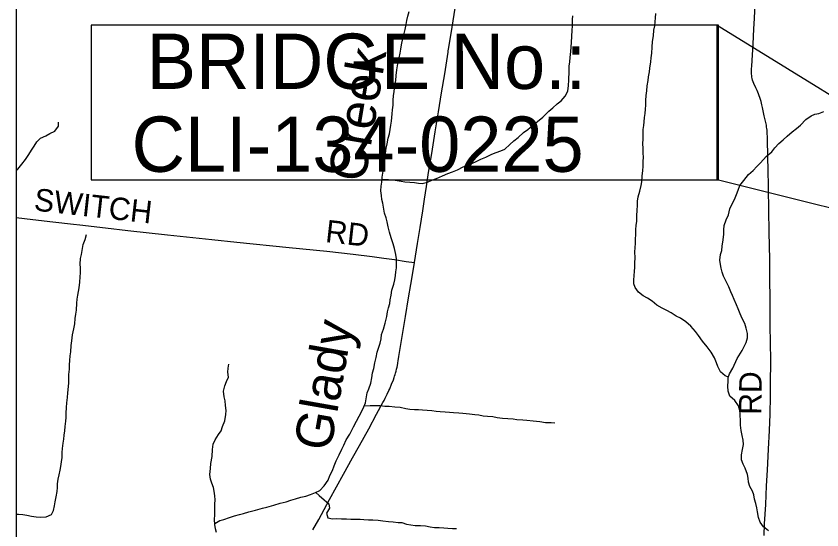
# Model space of a CAD drawing. Extents: x 0 to 48.6, y 0 to 22.
# Drawn here: x 2.1 to 4.141, y 17.154 to 18.455 of the extents above; entities that cross this region are included whole.
import ezdxf

# ---------------------------------------------------------------- set-up
doc = ezdxf.new("R2010")
doc.units = 0
for name, color, linetype in [('GM_X_Corporation', 7, 'Continuous'), ('GM_X_County_Road', 7, 'Continuous'), ('GM_X_County_Road_Text', 7, 'Continuous'), ('GM_X_Minor_River', 7, 'Continuous'), ('GM_X_Minor_River_Text', 7, 'Continuous'), ('GM_X_Township_Road', 7, 'Continuous'), ('GM_X_Township_Road_Text', 7, 'Continuous'), ('SH_Data', 7, 'Continuous'), ('SH_Masking', 7, 'Continuous'), ('SH_Text', 7, 'Continuous')]:
    doc.layers.add(name, color=color, linetype=linetype)

msp = doc.modelspace()

# ---------------------------------------------------------------- linework, layer by layer
at = {"layer": 'GM_X_Corporation'}
for points in [[(8.9, 20.9), (2.1, 20.9), (2.1, 14.1)], [(5.5264, 17.0064), (5.8387, 17.2541), (6.5365, 17.7727), (6.4996, 17.9212), (6.3396, 18.6531), (6.2759, 18.9159), (6.0412, 19.8859), (5.8236, 20.7829), (5.795, 20.9), (2.1, 20.9), (2.1, 14.1)]]:
    msp.add_lwpolyline(points, dxfattribs=at)
at = {"layer": 'GM_X_County_Road'}
for points in [[(3.1088, 17.8315), (3.1166, 17.8799), (3.123, 17.9197), (3.1297, 17.9627), (3.134, 17.9922), (3.1391, 18.0235), (3.1446, 18.0591), (3.1526, 18.1076), (3.1614, 18.1622), (3.1699, 18.213), (3.1775, 18.2609), (3.1855, 18.3093), (3.194, 18.3643), (3.1945, 18.3676), (3.1951, 18.3714), (3.2016, 18.4112), (3.2071, 18.4437), (3.217, 18.5088)], [(3.9943, 17.1401), (3.9958, 17.1693), (3.9984, 17.2189), (4.0007, 17.266), (4.0029, 17.3057), (4.0055, 17.3591), (4.008, 17.4062), (4.0095, 17.4472), (4.0105, 17.4932), (4.011, 17.5379), (4.0111, 17.569), (4.0103, 17.6429), (4.0099, 17.6566), (4.0098, 17.6609), (4.01, 17.6758), (4.0096, 17.7305), (4.0093, 17.7983), (4.0088, 17.8387), (4.0075, 17.9082), (4.0068, 17.9642), (4.0056, 18.0201), (4.0046, 18.0704), (4.004, 18.0934), (4.0028, 18.1493), (4.0024, 18.1582), (4.0023, 18.1617), (4.0018, 18.1665), (4.0014, 18.1704), (4.0009, 18.1739), (4.0005, 18.1766), (4.0001, 18.1791), (3.9987, 18.1864), (3.995, 18.2028), (3.9903, 18.224), (3.9888, 18.2307), (3.9878, 18.2348), (3.9867, 18.2392), (3.9852, 18.2443), (3.9837, 18.2494), (3.9821, 18.2537), (3.9804, 18.2582), (3.9785, 18.2625), (3.9766, 18.2667), (3.975, 18.27), (3.9734, 18.2735), (3.9682, 18.2847), (3.9666, 18.289), (3.9654, 18.2931), (3.9642, 18.2976), (3.9636, 18.3012), (3.9631, 18.3054), (3.9629, 18.3088), (3.9627, 18.3122), (3.9628, 18.3175), (3.9628, 18.3215), (3.9632, 18.3289), (3.964, 18.3432), (3.9664, 18.3847), (3.9683, 18.4232), (3.9697, 18.4493), (3.9718, 18.4871)], [(2.8518, 17.1542), (2.8663, 17.181), (2.8801, 17.206), (2.894, 17.2317), (2.9293, 17.2952), (2.9521, 17.3366), (2.9695, 17.3682), (2.9931, 17.4105), (3.0129, 17.4471), (3.0292, 17.4771), (3.0318, 17.4822), (3.0346, 17.4877), (3.0371, 17.4926), (3.0397, 17.498), (3.0441, 17.5072), (3.0461, 17.5117), (3.0511, 17.5231), (3.0554, 17.534), (3.0574, 17.5399), (3.0586, 17.5434), (3.06, 17.5479), (3.0611, 17.5516), (3.0623, 17.5562), (3.0636, 17.5612), (3.0647, 17.5664), (3.0657, 17.5709), (3.0668, 17.5769), (3.0679, 17.5832), (3.0686, 17.5874), (3.0696, 17.5936), (3.086, 17.6947), (3.0937, 17.742), (3.0997, 17.7756), (3.1054, 17.8106), (3.1088, 17.8315)]]:
    msp.add_lwpolyline(points, dxfattribs=at)
at = {"layer": 'GM_X_Minor_River'}
for points in [[(3.0267, 18.0425), (3.0435, 18.0417), (3.0537, 18.0408), (3.0655, 18.0388), (3.0753, 18.0375), (3.0848, 18.0359), (3.097, 18.0349), (3.1087, 18.034), (3.1193, 18.0324), (3.1288, 18.0315), (3.1422, 18.0351), (3.1529, 18.0403), (3.1643, 18.0443), (3.1796, 18.051), (3.193, 18.0565), (3.2056, 18.0613), (3.2182, 18.0664), (3.2323, 18.0738), (3.2419, 18.0775), (3.2556, 18.083), (3.2652, 18.0874), (3.2774, 18.093), (3.29, 18.0985), (3.3049, 18.1055), (3.3156, 18.1096), (3.3274, 18.114), (3.3378, 18.1184), (3.3501, 18.13), (3.3605, 18.1397), (3.3716, 18.1479), (3.3847, 18.1603), (3.3962, 18.1685), (3.4077, 18.1782), (3.4204, 18.1883), (3.4338, 18.1995), (3.4492, 18.2145), (3.4592, 18.2235), (3.47, 18.2332), (3.4803, 18.2411), (3.4907, 18.2523), (3.497, 18.2651), (3.4991, 18.2799), (3.5, 18.2932), (3.5003, 18.3163), (3.5009, 18.3289), (3.5022, 18.3399), (3.5031, 18.3505), (3.5048, 18.366), (3.5061, 18.3766), (3.507, 18.3891), (3.5081, 18.4187), (3.5091, 18.4309), (3.5093, 18.4464), (3.5098, 18.4563)], [(3.0558, 18.2534), (3.0571, 18.2648), (3.0592, 18.2788), (3.0617, 18.292), (3.0626, 18.3053), (3.0643, 18.3193), (3.0656, 18.3299), (3.0676, 18.3398), (3.07, 18.3496), (3.0725, 18.3614), (3.0745, 18.372), (3.0762, 18.3826), (3.0794, 18.3985), (3.0826, 18.4113), (3.085, 18.4219), (3.0875, 18.4341), (3.0899, 18.4447), (3.0919, 18.4549), (3.0951, 18.467)], [(3.904, 17.5414), (3.8957, 17.5447), (3.8844, 17.5544), (3.877, 17.5681), (3.8741, 17.5777), (3.8685, 17.5903), (3.86, 17.6044), (3.8503, 17.6175), (3.838, 17.6324), (3.8283, 17.647), (3.8204, 17.657), (3.8092, 17.6704), (3.7961, 17.6812), (3.7829, 17.6901), (3.772, 17.6959), (3.7592, 17.7037), (3.7482, 17.7099), (3.7365, 17.7157), (3.723, 17.7231), (3.7106, 17.7339), (3.6989, 17.7409), (3.6883, 17.7467), (3.6763, 17.756), (3.6677, 17.7679), (3.6648, 17.7774), (3.6646, 17.7869), (3.6651, 17.7987), (3.666, 17.8085), (3.6669, 17.8199), (3.6674, 17.8298), (3.6676, 17.8442), (3.667, 17.8579), (3.6679, 17.8692), (3.6688, 17.8799), (3.669, 17.8909), (3.6695, 17.9026), (3.6697, 17.9152), (3.6706, 17.925), (3.6719, 17.936), (3.6724, 17.9497), (3.673, 17.9641), (3.6735, 17.9762), (3.6741, 17.9872), (3.6754, 17.9978), (3.6797, 18.0118), (3.6833, 18.0262), (3.6846, 18.0361), (3.6855, 18.0497), (3.6873, 18.0641), (3.6882, 18.0744), (3.6883, 18.0876), (3.6888, 18.0979), (3.6882, 18.1081), (3.688, 18.1199), (3.6874, 18.1325), (3.6883, 18.1442), (3.6881, 18.1564), (3.6879, 18.1681), (3.6895, 18.178), (3.6904, 18.1878), (3.6913, 18.1988), (3.693, 18.2087), (3.6943, 18.2197), (3.6948, 18.2299), (3.6953, 18.2421), (3.6959, 18.2546), (3.6972, 18.266), (3.6985, 18.2788), (3.7006, 18.2921), (3.7014, 18.3016), (3.7039, 18.3145), (3.7048, 18.3239), (3.7073, 18.3399), (3.7085, 18.3501), (3.7098, 18.3615), (3.7108, 18.3766), (3.7121, 18.391), (3.7142, 18.4051), (3.7152, 18.4198), (3.7176, 18.4308), (3.7185, 18.4411), (3.719, 18.4509), (3.7203, 18.4623)], [(2.6032, 17.1707), (2.6156, 17.1779), (2.6263, 17.1808), (2.6404, 17.1859), (2.653, 17.1899), (2.6656, 17.1936), (2.6762, 17.1961), (2.6896, 17.1997), (2.7064, 17.2041), (2.7239, 17.2091), (2.7353, 17.2117), (2.7529, 17.2171), (2.7689, 17.2219), (2.7838, 17.2258), (2.7956, 17.2295), (2.8078, 17.2331), (2.8208, 17.2368), (2.8337, 17.2396), (2.8455, 17.2436), (2.8585, 17.2488), (2.8696, 17.2543), (2.8804, 17.2656), (2.8905, 17.2799), (2.8944, 17.2924), (2.9014, 17.3048), (2.9054, 17.3165), (2.9105, 17.329), (2.9179, 17.3444), (2.9249, 17.3584), (2.9304, 17.3686), (2.9363, 17.3822), (2.9452, 17.3965), (2.9542, 17.4153), (2.9624, 17.43), (2.9686, 17.4425), (2.9748, 17.4534), (2.9803, 17.4663), (2.9846, 17.4765), (2.9892, 17.5014), (2.9931, 17.5113), (2.9986, 17.526), (3.0011, 17.5396), (3.0028, 17.5521), (3.0056, 17.5631), (3.0088, 17.5775), (3.0116, 17.5911), (3.0148, 17.604), (3.018, 17.6146), (3.022, 17.6274), (3.0244, 17.638), (3.0257, 17.6494), (3.0308, 17.6626), (3.0348, 17.6781), (3.0388, 17.6944), (3.0409, 17.7065), (3.0433, 17.7168), (3.0461, 17.7277), (3.0474, 17.7372), (3.0495, 17.7489), (3.0515, 17.7611), (3.0563, 17.7766), (3.0591, 17.7872), (3.0611, 17.7985), (3.062, 17.808), (3.0637, 17.8182), (3.0638, 17.8308), (3.0636, 17.8406), (3.0618, 17.852), (3.0586, 17.8665), (3.055, 17.8787), (3.0499, 17.8936), (3.0459, 17.9084), (3.0426, 17.9214), (3.0398, 17.9343), (3.0369, 17.9446), (3.0332, 17.9564), (3.0308, 17.9713), (3.0286, 17.9815), (3.0265, 17.9911), (3.0251, 18.001), (3.0241, 18.0131), (3.0247, 18.0249), (3.0259, 18.0347), (3.0272, 18.0476), (3.0297, 18.0624), (3.031, 18.0738), (3.0323, 18.0863), (3.0332, 18.0961), (3.0353, 18.1079), (3.0373, 18.1208), (3.0394, 18.1317), (3.0426, 18.1465), (3.0454, 18.1571), (3.0488, 18.1791), (3.0504, 18.1893), (3.0513, 18.1988), (3.0526, 18.2083), (3.0535, 18.2181), (3.0547, 18.2295), (3.0549, 18.2428), (3.0558, 18.2534)], [(3.8883, 17.8732), (3.8908, 17.8888), (3.8925, 17.9028), (3.8923, 17.9138), (3.8936, 17.9255), (3.8983, 17.9391), (3.9042, 17.9524), (3.9078, 17.9671), (3.9137, 17.9803), (3.9195, 17.9909), (3.9242, 18.0037), (3.9289, 18.0143), (3.9333, 18.0268), (3.9429, 18.0388), (3.9549, 18.0546), (3.9664, 18.0643), (3.9761, 18.0744), (3.9857, 18.0842), (4, 18.1003), (4.0138, 18.1115), (4.0215, 18.1217), (4.0319, 18.1325), (4.0427, 18.1423), (4.0527, 18.1513), (4.0654, 18.1621), (4.0765, 18.1711), (4.0869, 18.1789), (4.1003, 18.1932), (4.1138, 18.2029), (4.1233, 18.2073), (4.1328, 18.2087), (4.1458, 18.2142)], [(2.1, 18.0637), (2.1045, 18.0675), (2.1142, 18.0807), (2.1234, 18.0927), (2.1323, 18.1047), (2.1386, 18.1161), (2.1459, 18.1262), (2.1521, 18.1371), (2.1621, 18.1465), (2.1751, 18.1524), (2.1851, 18.1584), (2.1981, 18.1643), (2.2074, 18.1767), (2.2075, 18.1865)], [(2.2495, 17.6894), (2.2511, 17.7008), (2.2528, 17.711), (2.2538, 17.7285), (2.2543, 17.7387), (2.256, 17.7486), (2.2596, 17.7675), (2.2613, 17.7815), (2.2619, 17.7952), (2.2632, 17.805), (2.2633, 17.8176), (2.2619, 17.8275), (2.2629, 17.8415), (2.2657, 17.8517), (2.2702, 17.8767), (2.2749, 17.8899), (2.2781, 17.9024)], [(4.0055, 17.1519), (3.9931, 17.162), (3.9841, 17.1742), (3.9801, 17.1853), (3.9776, 17.2001), (3.9763, 17.2104), (3.9734, 17.2211), (3.9701, 17.2325), (3.968, 17.2428), (3.9647, 17.2523), (3.9584, 17.2645), (3.9551, 17.2756), (3.9541, 17.2851), (3.9523, 17.295), (3.9461, 17.311), (3.9413, 17.3209), (3.9376, 17.3316), (3.9374, 17.3445), (3.9399, 17.3578), (3.9423, 17.3707), (3.9417, 17.3813), (3.9388, 17.3931), (3.9364, 17.4064), (3.9346, 17.4197), (3.9348, 17.4323), (3.9338, 17.4437), (3.9339, 17.4531), (3.93, 17.4688), (3.9203, 17.4822), (3.9079, 17.493), (3.9031, 17.5056), (3.9025, 17.5181), (3.9038, 17.5306), (3.9036, 17.5401), (3.9068, 17.5499), (3.9153, 17.5642), (3.9259, 17.588), (3.9391, 17.6083), (3.9441, 17.6189), (3.9488, 17.6287), (3.9524, 17.6408), (3.9522, 17.6518), (3.9489, 17.6652), (3.9453, 17.6774), (3.939, 17.69), (3.9335, 17.7018), (3.9287, 17.7144), (3.9247, 17.7243), (3.9188, 17.7377), (3.914, 17.7476), (3.9099, 17.7572), (3.9055, 17.7697), (3.9, 17.7797), (3.8918, 17.7969), (3.8885, 17.8072), (3.886, 17.8167), (3.8839, 17.8266), (3.8821, 17.8376), (3.8838, 17.852), (3.8874, 17.8622), (3.8883, 17.8732)], [(2.1, 17.1942), (2.1061, 17.1944), (2.1171, 17.1931), (2.1269, 17.1914), (2.139, 17.1894), (2.1504, 17.1873), (2.1618, 17.1868), (2.1759, 17.187), (2.1892, 17.1933), (2.1943, 17.2035), (2.1971, 17.2156), (2.1992, 17.2258), (2.2016, 17.2379), (2.2037, 17.2519), (2.2046, 17.2614), (2.2051, 17.2709), (2.2068, 17.2826), (2.2092, 17.2936), (2.2116, 17.3057), (2.2129, 17.3152), (2.2146, 17.3266), (2.2163, 17.3376), (2.2168, 17.3505), (2.2173, 17.3607), (2.2194, 17.3736), (2.2211, 17.3842), (2.2219, 17.3941), (2.2232, 17.4054), (2.2245, 17.416), (2.2258, 17.4297), (2.2264, 17.4392), (2.2269, 17.4502), (2.2278, 17.4646), (2.2287, 17.476), (2.2301, 17.4896), (2.2314, 17.501), (2.2336, 17.5256), (2.2339, 17.548), (2.2348, 17.5617), (2.2354, 17.5723), (2.2359, 17.5829), (2.2372, 17.5951), (2.2385, 17.6053), (2.2398, 17.6209), (2.2411, 17.633), (2.2428, 17.6481), (2.2465, 17.6637), (2.2485, 17.6762), (2.2495, 17.6894)], [(2.5932, 17.3225), (2.5965, 17.3406), (2.5975, 17.3577), (2.5988, 17.3714), (2.6039, 17.3823), (2.6128, 17.3955), (2.619, 17.4053), (2.6226, 17.4158), (2.6289, 17.4309), (2.6314, 17.4465), (2.6319, 17.4563), (2.6305, 17.4696), (2.6295, 17.481), (2.627, 17.4913), (2.6253, 17.5058), (2.6285, 17.5194), (2.6329, 17.53), (2.6379, 17.5409), (2.6366, 17.5538), (2.6371, 17.5637), (2.6388, 17.5736)], [(2.9811, 17.4682), (2.9963, 17.4695), (3.0092, 17.4697), (3.0218, 17.4695), (3.0339, 17.4678), (3.0449, 17.4677), (3.0593, 17.4656), (3.073, 17.4647), (3.0874, 17.4618), (3.0969, 17.4602), (3.109, 17.4593), (3.1189, 17.4591), (3.1291, 17.4586), (3.1413, 17.4573), (3.153, 17.4564), (3.1636, 17.4552), (3.1743, 17.4539), (3.1864, 17.453), (3.1978, 17.4528), (3.208, 17.4519), (3.2213, 17.451), (3.2316, 17.4501), (3.2479, 17.448), (3.2619, 17.4467), (3.2718, 17.4454), (3.2828, 17.4434), (3.2941, 17.4425), (3.307, 17.4411), (3.318, 17.4387), (3.3321, 17.4374), (3.345, 17.4365), (3.3586, 17.4355), (3.3685, 17.4339), (3.3837, 17.4333), (3.3935, 17.4324), (3.4095, 17.4307), (3.4261, 17.4286), (3.4405, 17.4265), (3.455, 17.4259), (3.4645, 17.4254)], [(2.6076, 17.1476), (2.6054, 17.1572), (2.6033, 17.1678), (2.6027, 17.1803), (2.6029, 17.1925), (2.6035, 17.2084), (2.6036, 17.2198), (2.6045, 17.2304), (2.6035, 17.2403), (2.6018, 17.2521), (2.5996, 17.2616), (2.596, 17.2723), (2.5923, 17.2826), (2.5906, 17.2944), (2.5919, 17.3096), (2.5932, 17.3225)], [(2.8587, 17.2489), (2.8675, 17.2411), (2.8803, 17.2307), (2.8919, 17.2203), (2.8933, 17.2092), (2.8859, 17.1964), (2.8892, 17.185), (2.9017, 17.1826), (2.9119, 17.1828), (2.9237, 17.1826), (2.937, 17.1821), (2.948, 17.1816), (2.959, 17.1818), (2.9716, 17.1813), (2.981, 17.1804), (2.9928, 17.1799), (3.0035, 17.1801), (3.0171, 17.1792), (3.0285, 17.1775), (3.0433, 17.1758), (3.055, 17.1749), (3.0676, 17.1732), (3.077, 17.1727), (3.0891, 17.1687), (3.0998, 17.1675), (3.1108, 17.1654), (3.124, 17.1653), (3.1366, 17.1643), (3.1487, 17.1623), (3.1593, 17.1606), (3.1711, 17.1601), (3.1836, 17.1592), (3.1938, 17.1587), (3.2056, 17.1581), (3.2151, 17.1576)]]:
    msp.add_lwpolyline(points, dxfattribs=at)
at = {"layer": 'GM_X_Township_Road'}
for points in [[(2.1, 17.9451), (2.1422, 17.9401), (2.1929, 17.9345), (2.2455, 17.9283)], [(2.2455, 17.9283), (2.2614, 17.9265), (2.3268, 17.9191), (2.383, 17.9128), (2.4831, 17.9016), (2.5961, 17.8896), (2.6586, 17.8829), (2.7915, 17.8694), (2.8867, 17.86), (2.954, 17.8524), (3.0021, 17.8464), (3.0311, 17.8426), (3.0581, 17.8388), (3.0883, 17.8344), (3.1088, 17.8315)]]:
    msp.add_lwpolyline(points, dxfattribs=at)
at = {"layer": 'SH_Data'}
msp.add_line((2.1, 20.9), (2.1, 14.1), dxfattribs=at)
at = {"layer": 'SH_Masking'}
msp.add_lwpolyline([(3.8786, 18.4323), (2.2898, 18.4323), (2.2898, 18.0412), (3.8786, 18.0412)], close=True, dxfattribs=at)
at = {"layer": 'SH_Text'}
for points in [[(2.2898, 18.0412), (3.8757, 18.0412), (3.8757, 18.4323), (2.2898, 18.4323)], [(3.8757, 18.4323), (4.9445, 17.7738), (3.8757, 18.0412)]]:
    msp.add_lwpolyline(points, close=True, dxfattribs=at)

# ---------------------------------------------------------------- texts
at = {"layer": 'GM_X_County_Road_Text'}
msp.add_text('RD', height=0.05682, rotation=89.5254, dxfattribs=at).set_placement((3.9875, 17.4458))
at = {"layer": 'GM_X_Minor_River_Text'}
for s, rotation, p in [('Creek', 80.5946, (2.983, 18.0319)), ('Glady', 80.0003, (2.8959, 17.3507))]:
    msp.add_text(s, height=0.0947, rotation=rotation, dxfattribs=at).set_placement(p)
at = {"layer": 'GM_X_Township_Road_Text'}
for s, rotation, p in [('SWITCH', 353.6023, (2.1434, 17.9634)), ('RD', 353.5519, (2.8815, 17.8834))]:
    msp.add_text(s, height=0.05682, rotation=rotation, dxfattribs=at).set_placement(p)
at = {"layer": 'SH_Text'}
for s, p in [('BRIDGE No.:', (2.4308, 18.2711)), ('CLI-134-0225', (2.3925, 18.0611))]:
    msp.add_text(s, height=0.14, dxfattribs=at).set_placement(p)

doc.saveas('drawing.dxf')
